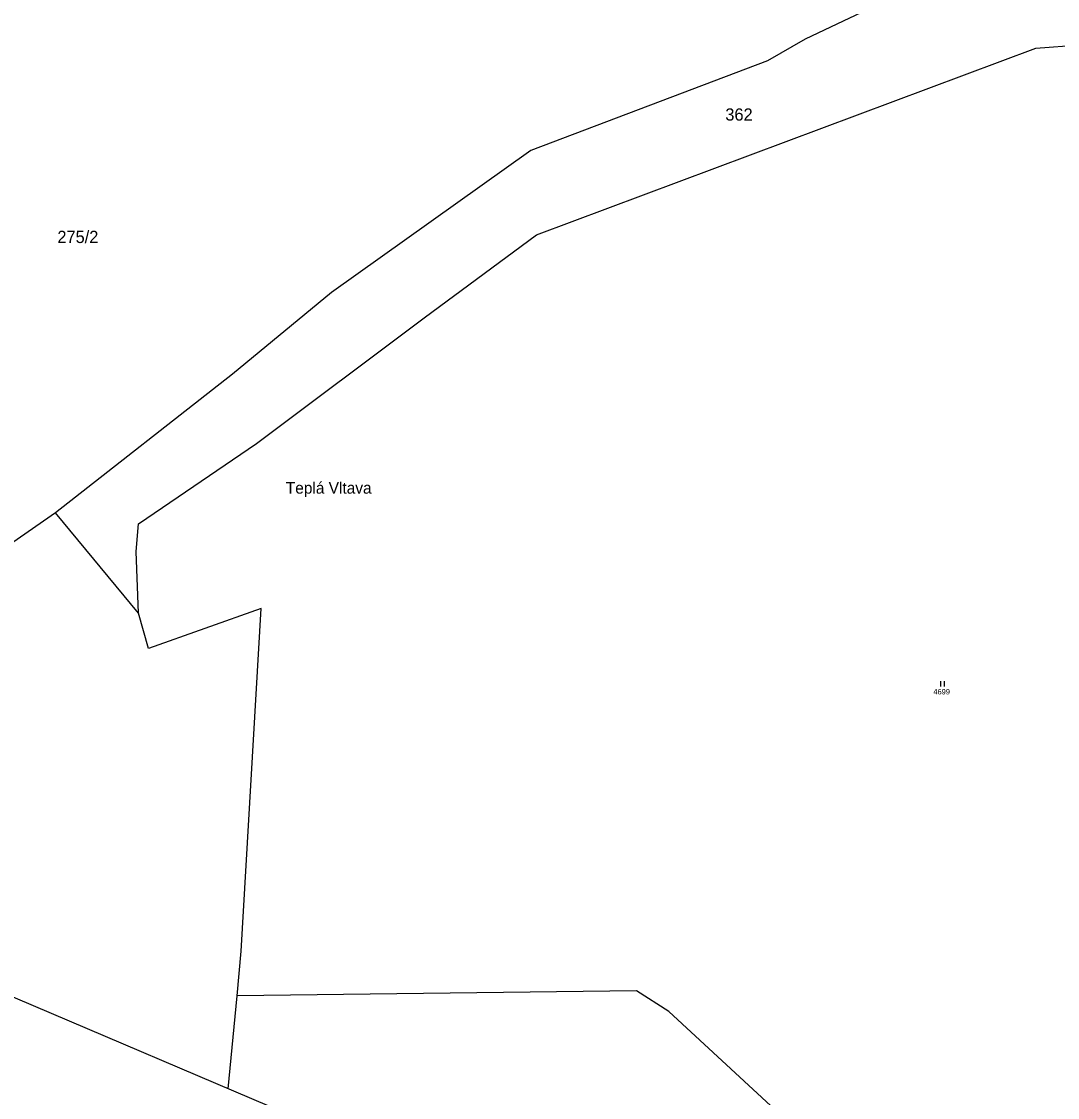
# Model space of a CAD drawing. Extents: x -805826 to -803822, y -1165880 to -1164382.
# Drawn here: x -805401.4 to -805114.2, y -1165376.6 to -1165078.1 of the extents above; entities that cross this region are included whole.
import ezdxf

# ---------------------------------------------------------------- set-up
doc = ezdxf.new("R2010")
doc.units = 0
for name, color, linetype in [('Default', 7, 'Continuous'), ('formát', 7, 'Continuous'), ('kn_celek - Cisla pozemkovych parcel', 7, 'Continuous'), ('kn_celek - Dalsi prvky mapy popis', 7, 'Continuous'), ('kn_celek - Hranice KU 1_2880', 7, 'Continuous'), ('kn_celek - Hranice parcel', 7, 'Continuous'), ('kn_celek - Znacky kultur', 7, 'Continuous')]:
    doc.layers.add(name, color=color, linetype=linetype)

# ---------------------------------------------------------------- blocks, each defined once
blk = doc.blocks.new('306')
at = {"layer": 'Default'}
for p, q in [((-5.2, 0), (-5.2, 15)), ((4.8, 0), (4.8, 15))]:
    blk.add_line(p, q, dxfattribs=at)

msp = doc.modelspace()

# ---------------------------------------------------------------- linework, layer by layer
at = {"layer": 'formát'}
msp.add_line((-805269.53, -1165405.94), (-805826.05, -1165169.15), dxfattribs=at)
at = {"layer": 'kn_celek - Hranice KU 1_2880'}
for p, q in [((-805258.7, -1165137.26), (-805120.21, -1165085.52)), ((-805120.21, -1165085.52), (-805107.91, -1165084.54)), ((-805289.78, -1165160.28), (-805258.7, -1165137.26)), ((-805336.33, -1165195.23), (-805289.78, -1165160.28)), ((-805369, -1165217.46), (-805336.33, -1165195.23)), ((-805392, -1165214.47), (-805443.52, -1165250.14)), ((-805369, -1165242.28), (-805392, -1165214.47)), ((-805369.7, -1165225.11), (-805369, -1165217.46)), ((-805369, -1165242.28), (-805369.7, -1165225.11)), ((-805366.23, -1165252.04), (-805369, -1165242.28)), ((-805334.96, -1165240.97), (-805366.23, -1165252.04)), ((-805340.59, -1165336.07), (-805334.96, -1165240.97)), ((-805341.68, -1165348.41), (-805340.59, -1165336.07)), ((-805344.13, -1165374.2), (-805341.68, -1165348.41))]:
    msp.add_line(p, q, dxfattribs=at)
at = {"layer": 'kn_celek - Hranice parcel'}
for p, q in [((-805138.61, -1165061.4), (-805184.2, -1165082.97)), ((-805184.2, -1165082.97), (-805194.65, -1165088.98)), ((-805258.7, -1165137.26), (-805120.21, -1165085.52)), ((-805120.21, -1165085.52), (-805107.91, -1165084.54)), ((-805194.65, -1165088.98), (-805260.26, -1165113.86)), ((-805260.26, -1165113.86), (-805315.54, -1165153.26)), ((-805289.78, -1165160.28), (-805258.7, -1165137.26)), ((-805315.54, -1165153.26), (-805342.99, -1165175.91)), ((-805336.33, -1165195.23), (-805289.78, -1165160.28)), ((-805342.99, -1165175.91), (-805392, -1165214.47)), ((-805369, -1165217.46), (-805336.33, -1165195.23)), ((-805369.7, -1165225.11), (-805369, -1165217.46)), ((-805369, -1165242.28), (-805369.7, -1165225.11)), ((-805366.23, -1165252.04), (-805369, -1165242.28)), ((-805334.96, -1165240.97), (-805366.23, -1165252.04)), ((-805340.59, -1165336.07), (-805334.96, -1165240.97)), ((-805341.68, -1165348.41), (-805340.59, -1165336.07)), ((-805230.97, -1165347), (-805341.68, -1165348.41)), ((-805222.01, -1165352.8), (-805230.97, -1165347)), ((-805344.13, -1165374.2), (-805341.68, -1165348.41)), ((-805192.49, -1165380.04), (-805222.01, -1165352.8))]:
    msp.add_line(p, q, dxfattribs=at)

# ---------------------------------------------------------------- block references
at = {"layer": 'kn_celek - Znacky kultur', "xscale": 0.1, "yscale": 0.10000000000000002}
msp.add_blockref('306', (-805146.02, -1165262.61), dxfattribs=at)

# ---------------------------------------------------------------- texts
at = {"layer": 'kn_celek - Cisla pozemkovych parcel'}
for s, height, p in [('362', 3.4, (-805206.31, -1165105.61)), ('275/2', 3.4, (-805391.52, -1165139.57)), ('4699', 1.5, (-805148.63, -1165264.81))]:
    msp.add_text(s, height=height, dxfattribs=at).set_placement(p)
at = {"layer": 'kn_celek - Dalsi prvky mapy popis'}
msp.add_text('Teplá Vltava', height=3.2, dxfattribs=at).set_placement((-805328.17, -1165209.11))

doc.saveas('drawing.dxf')
